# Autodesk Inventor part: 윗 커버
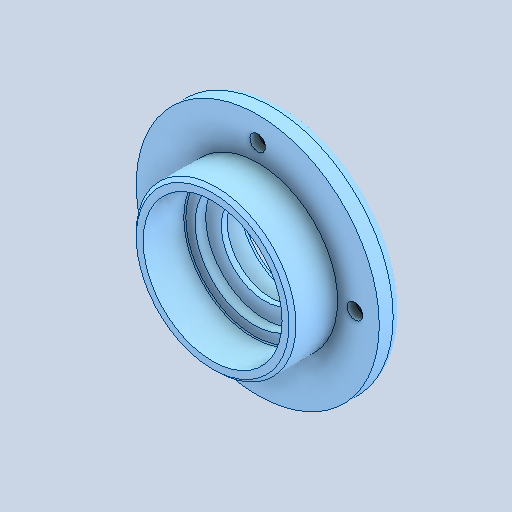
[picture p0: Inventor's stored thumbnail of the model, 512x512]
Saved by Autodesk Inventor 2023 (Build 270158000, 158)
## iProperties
Created: 2025-04
Part Number: 윗 커버
Material: 알루미늄 6061
Document SubType Name: Modeling
Designer: user
Density: 2.71 g/cm^3
Appearance: 기본값
Company: 한국ATC센터
Author: jhkim
Revision Number: 1
Sending System: Autodesk Inventor 2026
Preprocessor: ST-DEVELOPER v20.1
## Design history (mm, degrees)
feature "솔리드1"
node "솔리드2"
